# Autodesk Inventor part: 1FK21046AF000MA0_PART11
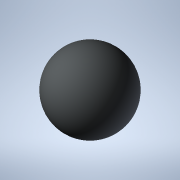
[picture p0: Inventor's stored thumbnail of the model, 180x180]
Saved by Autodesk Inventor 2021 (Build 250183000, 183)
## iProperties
Created: 2025-04
Part Number: 1FK21046AF000MA0_PART11
Material: Generic
Catalog Web Link: www.3dfindit.com
Description: -Servo synchronous motor
Document SubType Name: Modeling
Designer: psAdmin
Mass: 0.137258 g
Surface Area: 1.2868 cm^2
Volume: 0.137258 cm^3
Density: 1 g/cm^3
Appearance: PSOLRGB-212-217-219
Category: PARTsolutions
Title: 1FK21046AF000MA0_PART11
Author: Cadenas PARTsolutions
Comments: Servo synchronous motor
Sending System: PARTsolutions
Preprocessor: ST-DEVELOPER v19.3
PSOL_IDENT_0: {$CADENAS_DATA/23d-libs/siemens_ag/_cat_/1c/1f/1fk21046af000ma0.prj},216 {VTYP=3D},{NB=1FK21046AF000
PSOL_IDENT_1: MA0_PART11},{LINA=1FK21046AF000MA0_PART11},{NN=1FK21046AF000MA0_PART11},{NOPRJ=TRUE},{DATE=19.08.202
PSOL_IDENT_2: 5 14:00:28},{GEOMDATE=30.07.2025 02:02:08},{VERSION=},{LINEID=10},{WBVAR=},{WBNUMERIC=}  {NB=1FK2104
PSOL_IDENT_3: 6AF000MA0_PART11},{LINA=1FK21046AF000MA0_PART11},{KT=DUMMY},{PREVIEW=../../../_pool_/cb/72/p_d211_xx
PSOL_IDENT_4: _00434j.png},{DESCSHORT=SIMOTICS S-1FK2 HD, SINAMICS S210 3AC 400V-480V, 3.2 Nm, 3000 rpm},{DESCLONG=
PSOL_IDENT_5: SIMOTICS S-1FK2 HD servo motor M0=3.2 Nm; PN = 1 kW at nN=3000 rpm (380-480 V); PN = 0.5 kW at nN=15
PSOL_IDENT_6: 00 rpm (200-240 V); degree of protection IP64; cylindrical shaft D19x40mm; absolute encoder 22-bit +
PSOL_IDENT_7: 12-bit multiturn (encoder AM22DQC); with OCC interface; plug size M17, rotatable; SIMOTICS S-1FK2 s
PSOL_IDENT_8: ervomotorfor a wide range of uses in industrial environments. SIMOTICS S‑1FK2 servomotors are compac
PSOL_IDENT_9: t synchronous motors with a high dynamic performance that set themselves apart as a result of their
PSOL_IDENT_10: high power density, degree of protection and overload capability. The motors are available in two va
PSOL_IDENT_11: riants: as High Dynamic variant (highest dynamic performance as a result of the low intrinsic moment
PSOL_IDENT_12: of inertia for applications demanding a high dynamic performance with low moved masses) - and as Co
PSOL_IDENT_13: mpact variant (precise and stable closed-loop control for medium up to large moved masses as a resul
PSOL_IDENT_14: t of a medium intrinsic moment of inertia). SIMOTICSS‑1FK2 servomotors fully exploit their strengths
PSOL_IDENT_15: in a system with the SINAMICSS210 frequency converter and simple connection using the one cable con
PSOL_IDENT_16: nection (OCC). Advantages include the short control and positioning times, fast and precise correcti
PSOL_IDENT_17: on of disturbing quantities as well as stable control with a high dynamic performance. The servo mot
PSOL_IDENT_18: ors can be configured to address a wide range of requirements. For example with and without holding
PSOL_IDENT_19: brake, IP64 or IP65 degree of protection, singleturn or multiturn absolute encoders - to name just a
PSOL_IDENT_20: few. Further, the servomotors are available in different shaft heights extending from 20 to 100. A
PSOL_IDENT_21: shaft sealing ring is available to achieve an IP65 degree of protection and for subsequent mounting
PSOL_IDENT_22: at the motor or as spare part. SIMOTICS - the optimum motor for each and every motion control applic
PSOL_IDENT_23: ation.},{INTNO=195125049666},{SUPPLIERALTNO=1FK2104-6AF00-0MA0},{MANUID=1FK21046AF000MA0},{MANUNAME=
PSOL_IDENT_24: Siemens},{MANUTYPEDESC=Synchronous motor 1FK2-HD 3.2 NM},{AAU732=SIMOTICS},{AAO057=S-1FK2},{AAU734=S
PSOL_IDENT_25: IMOTICS S-1FK2 HD servo motor M0=3.2 Nm; PN = 1 kW at nN=3000 rpm (380-480 V); PN = 0.5 kW at nN=150
PSOL_IDENT_26: 0 rpm (200-240 V); degree of protection IP64; cylindrical shaft D19x40mm; absolute encoder 22-bit +
PSOL_IDENT_27: 12-bit multiturn (encoder AM22DQC); with OCC interface; plug size M17, rotatable;},{AAW338=Synchrono
PSOL_IDENT_28: us motor 1FK2-HD 3.2 NM},{AAO742=SIMOTICS},{AAO663=4042948694374},{NOCUPEROU=1},{PRICEQUANTITY=1},{Q
PSOL_IDENT_29: UANTITYMIN=1},{QUANTITYINT=1},{CTN=85015220},{COO=DE},{AAO676=1FK2104-6AF00-0MA0},{AAO677=Siemens AG
PSOL_IDENT_30: },{ORDERUNIT=C62},{CONTENTUNIT=C62}
NB: 1FK21046AF000MA0_PART11
NT: Servo synchronous motor
NBSYN: $MANUID._PART11
LINA: 1FK21046AF000MA0_PART11
CATALOG: SIEMENS
PREVIEW: ../../../_pool_/cb/72/p_d211_xx_00434j.png
DESCSHORT: SIMOTICS S-1FK2 HD, SINAMICS S210 3AC 400V-480V, 3.2 Nm, 3000 rpm
DESCLONG: SIMOTICS S-1FK2 HD servo motor M0=3.2 Nm; PN = 1 kW at nN=3000 rpm (380-480 V); PN = 0.5 kW at nN=1500 rpm (200-240 V); degree of protection IP64; cylindrical s
INTNO: 195125049666
SUPPLIERALTNO: 1FK2104-6AF00-0MA0
MANUID: 1FK21046AF000MA0
MANUNAME: Siemens
MANUTYPEDESC: Synchronous motor 1FK2-HD 3.2 NM
AAU732: SIMOTICS
AAO057: S-1FK2
AAU734: SIMOTICS S-1FK2 HD servo motor M0=3.2 Nm; PN = 1 kW at nN=3000 rpm (380-480 V); PN = 0.5 kW at nN=1500 rpm (200-240 V); degree of protection IP64; cylindrical s
AAW338: Synchronous motor 1FK2-HD 3.2 NM
AAO742: SIMOTICS
AAO663: 4042948694374.0
NOCUPEROU: 1
PRICEQUANTITY: 1
QUANTITYMIN: 1
QUANTITYINT: 1
CTN: 85015220
COO: DE
ARTICLENO: 1FK21046AF000MA0_PART11
BOMINFO: 1FK21046AF000MA0_PART11
CREATOR: CADENAS GmbH
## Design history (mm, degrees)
feature "2025_04_17_15_39_11_0412"
body "Solid1"
